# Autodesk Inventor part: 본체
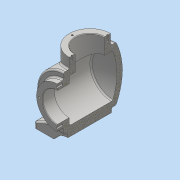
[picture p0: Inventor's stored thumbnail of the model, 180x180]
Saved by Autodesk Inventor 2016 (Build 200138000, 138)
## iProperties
Created: 2021-04
Part Number: 본체
Material: Generic
Document SubType Name: Modeling
Designer: User
Density: 1 g/cm^3
Appearance: Default
Author: User
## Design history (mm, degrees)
sketch "스케치1"
  geometry: L1 (0, 0)-(-120, 0); L2 (0, 0)-(0, 50); L3 (0, 50)-(-108, 50); L4 (-108, 50)-(-108, 38); L5 (-108, 38)-(-120, 38); L6 (-120, 38)-(-120, 0)
  constraints: 13 end point, 4 perpendicular, 1 horizontal, 1 vertical
  dimensions: "d2" = 12 distance of L4.end L5.end; "d3" = 100 diameter of L3 L1; "d4" = 76 diameter of L5 L1; "d6" = 108 distance of L2.end L3.end
revolve "회전1" sketch "스케치1" stored, may be unused: angle "d7" = 90 deg
sketch "스케치2"
  geometry: L1 (-108, 50)-(0, 50) reference; L2 (0, -50)-(0, 50) reference; L3 (-108, -50)-(0, -50) reference; L4 (-11.664, 50)-(0, 50); L5 (0, 50)-(0, 0); L6 (0, 0)-(-37.024, 0); A1 r 113 centre (-113, 0) between (0, 0) and (-11.664, 50)
  constraints: 6 end point, 4 point on circle, 2 horizontal, 2 point on line, 1 centre point
  dimensions: "d8" = 226 diameter of A1
revolve "회전2" sketch "스케치2" stored, may be unused: angle "d9" = 90 deg
sketch "스케치3"
  geometry: L1 (-120, -38)-(-120, 38) reference; L2 (-120, 0)-(0, 0); L3 (-120, 0)-(-120, 27); L4 (-120, 27)-(-98, 27); L5 (-98, 27)-(-98, 40); L6 (-98, 40)-(-18.084, 40); A1 r 113 centre (-113, 0) between (-11.664, -50) and (-11.664, 50) reference; A2 r 103 centre (-113, 0) between (-10, 0) and (-18.084, 40)
  constraints: 10 end point, 2 horizontal, 2 perpendicular, 2 point on circle, 2 point on line, 1 centre point, 1 midpoint
  dimensions: "d10" = 10 radial gap between concentric circles of A1 A2; "d11" = 54 diameter of L4 L2; "d12" = 22 distance of L3.end L4.end; "d13" = 80 diameter of L6 L2
revolve "회전3" sketch "스케치3" stored, may be unused: angle "d14" = 90 deg
node "작업 평면1"
sketch "스케치4"
  geometry: L1 (-22.795, -44.501)-(-62, -62.783); L2 (-62, -62.783)-(-62, -72.783); L3 (62, -72.783)-(62, -62.783); L4 (62, -62.783)-(22.795, -44.501); L5 (-62, -72.783)-(-25.981, -72.783); L6 (25.981, -72.783)-(62, -72.783); A1 r 50 centre (0, 0) between (-22.795, -44.501) and (22.795, -44.501) reference; A2 r 30 centre (0, -87.783) between (25.981, -72.783) and (-25.981, -72.783); 2 further points
  constraints: 12 end point, 4 perpendicular, 4 point on circle, 2 vertical alignment, 1 centre point, 1 vertical
  dimensions: "d17" = 60 diameter of A2; "d19" = 124 distance between parallel lines of L3 L2; "d20" = 65 deg angle of L2 L1; "d21" = 65 deg angle of L3 L4; "d22" = 10 distance of L1.end L2.end; "d23" = 10 distance of L3.start L3.end
extrude "돌출1" join sketch "스케치4" distance "d24" = 80; taper "d25" = 0 deg
sketch "스케치5"
  geometry: L1 (-87.981, 0)-(-87.981, 80) reference; L2 (-51.962, 0)-(-87.981, 0) reference; 5 further points
  constraints: 2 horizontal alignment, 2 vertical alignment
  dimensions: "d26" = 108 distance of point (-79.981, 20) point (28.019, 20); "d27" = 8 distance from line of point (-79.981, 20) L1; "d28" = 20 distance from line of L2 point (-79.981, 20); "d29" = 40 distance of point (-79.981, 60) point (-79.981, 20)
hole "구멍1" sketch "스케치5" at (28.019, 20), (-79.981, 20), (-79.981, 60), (28.019, 60) diameter "d30" = 9; stored, may be unused: countersink angle "d34" = 90 deg, drill point angle "d36" = 118 deg; dims "d31" = 6, "d32" = 4, "d33" = 2, "d35" = 20
node "작업 평면2"
sketch "스케치6"
  geometry: L1 (-40.161, 67)-(-40.161, 53); L2 (-28.019, 67)-(-40.161, 67); L3 (-28.019, 53)-(-40.161, 53); L4 (-36.019, 0)-(-36.019, 80) reference; L5 (-36.019, 40)-(87.981, 40); L6 (87.981, 0)-(87.981, 80) reference; L7 (-28.019, 27)-(-40.161, 27); L8 (-28.019, 13)-(-40.161, 13); L9 (-40.161, 13)-(-40.161, 27); C1 r 4.5 at (-28.019, 60) reference; A1 r 7 centre (-28.019, 60) between (-28.019, 53) and (-28.019, 67); A2 r 7 centre (-28.019, 20) between (-28.019, 13) and (-28.019, 27); 2 further points
  constraints: 14 end point, 5 symmetric about line, 4 point on circle, 3 midpoint, 2 centre point, 1 coincident, 1 horizontal alignment, 1 parallel, 1 tangent, 1 vertical, 1 other
  dimensions: "d38" = 14 distance of L1.start L1.end; "d39" = 14 diameter of A1
extrude "돌출2" cut sketch "스케치6" distance "d40" = 20; taper "d41" = 0 deg
node "작업 평면3"
sketch "스케치7"
  geometry: L1 (-112, -8)-(-112, 88.336) reference; L2 (-12, -8)-(-112, -8) reference; C1 r 38 at (-62, 40.168); 3 further points
  constraints: 2 midpoint, 1 centre point, 1 horizontal alignment, 1 vertical alignment
  dimensions: "d43" = 76 diameter of C1
extrude "돌출3" join sketch "스케치7" stored distance "d44" = 80; taper "d45" = 0 deg
hole "구멍2" diameter "d48" = 54; stored, may be unused: countersink angle "d52" = 90 deg, drill point angle "d54" = 118 deg; dims "d49" = 6, "d50" = 4, "d51" = 2, "d53" = 8, "d55" = 10, "d56" = 10
sketch "스케치8"
  geometry: 2 further points
  constraints: 1 vertical alignment
  dimensions: "d57" = 32.5 distance of point (0, 0) point (0, 32.5)
hole "구멍3" sketch "스케치8" at (0, 32.5) diameter "d58" = 3.242; stored, may be unused: countersink angle "d62" = 90 deg, drill point angle "d64" = 118 deg; dims "d59" = 8, "d60" = 4, "d61" = 2, "d63" = 10
sketch "스케치9"
  geometry: C1 r 27 at (0, 0) reference; 2 further points
  constraints: 1 vertical alignment
  dimensions: "d68" = 32.5 distance of point (0, -32.5) C1.centre
hole "구멍4" sketch "스케치9" at (0, -32.5) diameter "d69" = 3.242; stored, may be unused: countersink angle "d73" = 90 deg, drill point angle "d75" = 118 deg; dims "d70" = 8, "d71" = 4, "d72" = 2, "d74" = 10
chamfer "모따기1" distance "d79" = 1; stored, may be unused: second distance "d80" = 2, angle "d81" = 45 deg
fillet "모깎기1" dims "d82" = 3
fillet "모깎기2" dims "d83" = 3
fillet "모깎기3" dims "d84" = 3
node "작업 평면4"
node "작업 평면5"
sketch "스케치11"
  geometry: 2 further points
  constraints: 1 coincident, 1 other
feature "엠보싱1" sketch "스케치11" dims "d2" = 12, "d3" = 100, "d4" = 76, "d6" = 108, "d86" = 0.5, "d87" = 0
fillet "모깎기4" dims "d88" = 3
node "솔리드1"
mirror "대칭1"
pattern_circular "원형 패턴1" dims angle "d66" = 360 deg
pattern_circular "원형 패턴2" dims angle "d77" = 360 deg
other parameters: "d18" = 15, "d37" = -4, "d42" = -142, "d85" = 0.5
